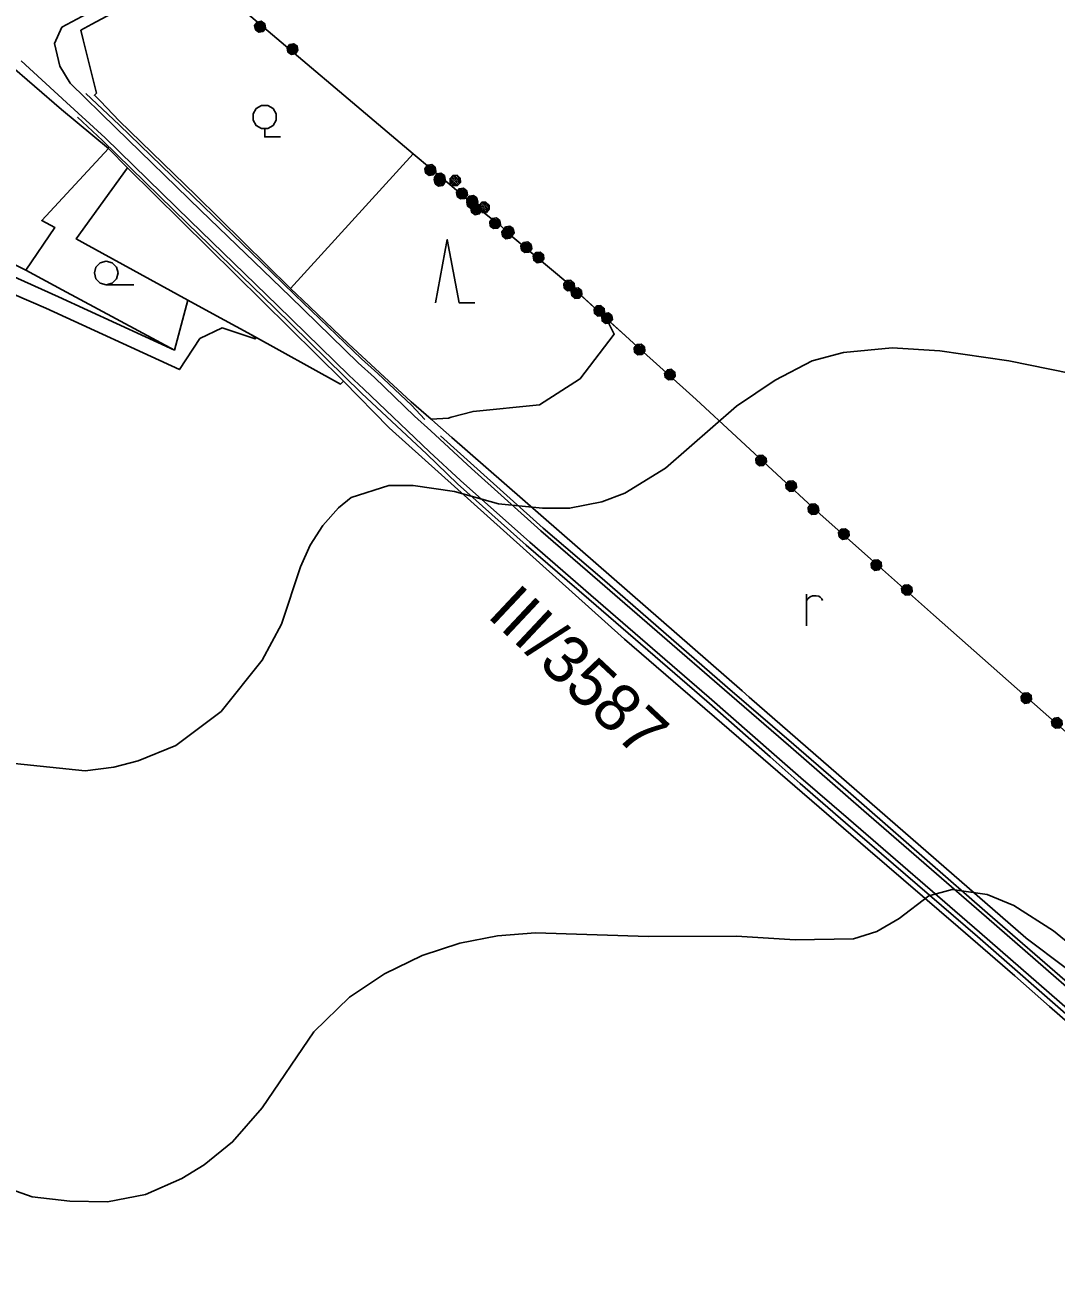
# Model space of a CAD drawing. Extents: x -645676 to -642474, y -1077513 to -1072613.
# Drawn here: x -643348.1 to -643021.2, y -1073485.7 to -1073092.2 of the extents above; entities that cross this region are included whole.
import ezdxf

# ---------------------------------------------------------------- set-up
doc = ezdxf.new("R2010")
doc.units = 0
for name, color, linetype in [('KULTURY_STAV', 7, 'Continuous'), ('KULTURY_ZNACKY', 7, 'Continuous'), ('Obvod_KP_', 7, 'Continuous'), ('OBVOD_PU', 7, 'Continuous'), ('P__kop___st_vaj_c_', 7, 'Continuous'), ('Popis_silnice_II__a_III__t__dy', 7, 'Continuous'), ('Silnice_II__t__dy_a_III__t__dy', 7, 'Continuous'), ('SPRAV_HR_STAV', 7, 'Continuous'), ('VRSTEVNICE', 7, 'Continuous')]:
    doc.layers.add(name, color=color, linetype=linetype)

# ---------------------------------------------------------------- blocks, each defined once
blk = doc.blocks.new('3$0400')
blk.add_lwpolyline([(0, 0), (-0.38, 0.1), (-0.65, 0.38), (-0.75, 0.75), (-0.65, 1.12), (-0.38, 1.4), (0, 1.5), (0.38, 1.4), (0.65, 1.12), (0.75, 0.75), (0.65, 0.38), (0.38, 0.1), (0, 0), (1.75, 0)])
blk = doc.blocks.new('3$0800')
blk.add_lwpolyline([(-0.75, 0), (0, 4), (0.75, 0), (1.75, 0)])
blk = doc.blocks.new('3$0500')
blk.add_lwpolyline([(0, 0.53), (-0.19, 0.53), (-0.53, 0.72), (-0.72, 1.06), (-0.72, 1.45), (-0.53, 1.79), (-0.19, 1.98), (0.2, 1.98), (0.54, 1.79), (0.73, 1.45), (0.73, 1.06), (0.54, 0.72), (0.2, 0.53), (0.01, 0.53), (0.01, 0), (1.01, 0)])
blk = doc.blocks.new('$479')
for points in [[(0, 0), (0, 1.27), (0, 2)], [(0, 1.6), (0.1, 1.73), (0.23, 1.84), (0.37, 1.89), (0.6, 1.9), (0.77, 1.87), (0.87, 1.8), (0.96, 1.7), (1, 1.6)]]:
    blk.add_lwpolyline(points)
blk = doc.blocks.new('2$0620')
for points in [[(-1.07, 0.32), (-0.88, 0.13), (-0.88, -0.14), (-1.07, -0.33), (-1.34, -0.33), (-1.53, -0.14), (-1.53, 0.13), (-1.34, 0.32), (-1.07, 0.32), (-1.08, 0.28), (-1.32, 0.28), (-1.4, 0.2), (-1, 0.2), (-0.92, 0.12), (-1.48, 0.12), (-1.48, 0.04), (-0.92, 0.04), (-0.92, -0.04), (-1.48, -0.04), (-1.48, -0.12), (-0.92, -0.12), (-1, -0.2), (-1.4, -0.2), (-1.32, -0.28), (-1.08, -0.28)], [(1.43, 0.32), (1.62, 0.13), (1.62, -0.14), (1.43, -0.33), (1.16, -0.33), (0.97, -0.14), (0.97, 0.13), (1.16, 0.32), (1.43, 0.32), (1.4, 0.28), (1.16, 0.28), (1.08, 0.2), (1.48, 0.2), (1.56, 0.12), (1, 0.12), (1, 0.04), (1.56, 0.04), (1.56, -0.04), (1, -0.04), (1, -0.12), (1.56, -0.12), (1.48, -0.2), (1.08, -0.2), (1.16, -0.28), (1.4, -0.28)]]:
    blk.add_lwpolyline(points)

msp = doc.modelspace()

# ---------------------------------------------------------------- linework, layer by layer
at = {"layer": 'KULTURY_STAV'}
for points in [[(-643296.21, -1073075.68), (-643290.86, -1073080.01), (-643287.81, -1073082.47), (-643285.35, -1073084.46), (-643283.33, -1073083.76), (-643281.92, -1073084.95), (-643224.95, -1073133.07), (-643263.86, -1073175.83), (-643261.75, -1073177.84), (-643263.86, -1073175.83), (-643293.86, -1073146.22), (-643318.19, -1073122.63), (-643324.08, -1073116.41), (-643326.04, -1073114.54), (-643325.4, -1073113.94), (-643329.62, -1073096.96), (-643330.38, -1073093.93), (-643326.83, -1073092.03), (-643317.54, -1073087.07), (-643312.22, -1073084.23), (-643296.21, -1073075.68)], [(-643326.83, -1073092.03), (-643330.38, -1073093.93), (-643329.62, -1073096.96), (-643325.4, -1073113.94), (-643326.04, -1073114.54), (-643324.08, -1073116.41), (-643318.19, -1073122.63), (-643293.86, -1073146.22), (-643263.86, -1073175.83), (-643261.75, -1073177.84), (-643260.18, -1073179.33), (-643245.44, -1073193.33), (-643225.66, -1073211.67), (-643219.31, -1073217.22), (-643218.12, -1073218.26), (-643212.7, -1073223), (-643167.1, -1073262.85), (-643120.73, -1073303.37), (-643118.51, -1073305.31), (-643118.49, -1073305.33), (-643030.79, -1073381.65), (-643030.66, -1073381.74), (-643018.34, -1073391)], [(-643353.64, -1073104.24), (-643336.43, -1073119.05), (-643321.53, -1073131.44), (-643342.76, -1073154.27), (-643338.61, -1073156.46), (-643347.83, -1073170.04), (-643361.09, -1073163.36), (-643387.69, -1073148.03), (-643398.24, -1073141.11), (-643395.1, -1073137.94), (-643387.69, -1073131.15), (-643381.32, -1073123.85), (-643380.09, -1073122.55), (-643353.64, -1073104.24)], [(-642998.75, -1073424.71), (-643023.32, -1073403.36), (-643034.23, -1073393.69), (-643052.25, -1073378.17), (-643080.91, -1073353.5), (-643157.97, -1073286.97), (-643232.56, -1073219.92), (-643247.12, -1073205.19), (-643315.57, -1073137.59), (-643321.53, -1073131.44), (-643336.43, -1073119.05), (-643353.64, -1073104.24)], [(-643321.53, -1073131.44), (-643315.57, -1073137.59), (-643331.82, -1073160.06), (-643328.97, -1073161.67), (-643296.42, -1073179.5), (-643300.68, -1073195.31), (-643336.26, -1073176.27), (-643347.83, -1073170.04), (-643338.61, -1073156.46), (-643342.76, -1073154.27), (-643321.53, -1073131.44)], [(-643224.95, -1073133.07), (-643213.42, -1073142.81), (-643210.36, -1073145.39), (-643200.78, -1073153.18), (-643197.26, -1073155.82), (-643194.66, -1073158.46), (-643180.49, -1073170.32), (-643176.63, -1073173.56), (-643163.66, -1073185.4), (-643161.27, -1073190.23), (-643172.2, -1073204.57), (-643172.22, -1073204.59), (-643184.91, -1073212.67), (-643206, -1073214.78), (-643212.98, -1073216.56), (-643213.8, -1073216.91), (-643219.31, -1073217.22), (-643225.66, -1073211.67), (-643245.44, -1073193.33), (-643260.18, -1073179.33), (-643261.75, -1073177.84), (-643263.86, -1073175.83), (-643224.95, -1073133.07)], [(-643376.35, -1073167.01), (-643341.42, -1073182.01), (-643299.07, -1073201.52), (-643292.57, -1073191.65), (-643285.58, -1073188.29), (-643275.03, -1073191.76), (-643274.84, -1073191.47), (-643276.29, -1073190.5), (-643289.7, -1073183.18), (-643296.42, -1073179.5), (-643328.97, -1073161.67), (-643331.82, -1073160.06), (-643315.57, -1073137.59)], [(-643315.57, -1073137.59), (-643247.12, -1073205.19), (-643232.56, -1073219.92), (-643157.97, -1073286.97), (-643080.91, -1073353.5), (-643052.25, -1073378.17), (-643034.23, -1073393.69), (-643023.32, -1073403.36), (-642998.75, -1073424.71), (-642972.5, -1073447.63), (-642919.91, -1073493.56)], [(-643405.6, -1073150.8), (-643361.09, -1073163.36), (-643347.83, -1073170.04), (-643336.26, -1073176.27), (-643300.68, -1073195.31), (-643337.38, -1073178.47), (-643371.97, -1073162.86), (-643405.6, -1073150.8)], [(-643371.97, -1073162.86), (-643337.38, -1073178.47), (-643300.68, -1073195.31), (-643296.42, -1073179.5), (-643289.7, -1073183.18), (-643276.29, -1073190.5), (-643274.84, -1073191.47), (-643275.03, -1073191.76), (-643285.58, -1073188.29), (-643292.57, -1073191.65), (-643299.07, -1073201.52), (-643341.42, -1073182.01), (-643376.35, -1073167.01)], [(-643018.34, -1073391), (-643030.66, -1073381.74), (-643030.79, -1073381.65), (-643118.49, -1073305.33), (-643118.51, -1073305.31), (-643120.73, -1073303.37), (-643167.1, -1073262.85), (-643212.7, -1073223), (-643218.12, -1073218.26), (-643219.31, -1073217.22), (-643213.8, -1073216.91), (-643212.98, -1073216.56), (-643206, -1073214.78), (-643184.91, -1073212.67), (-643172.22, -1073204.59), (-643172.2, -1073204.57), (-643161.27, -1073190.23), (-643163.66, -1073185.4)], [(-643163.66, -1073185.4), (-643157.69, -1073190.84), (-643155.17, -1073193.1), (-643135.23, -1073210.97), (-643096.95, -1073246.45), (-643080.03, -1073261.47), (-643060.08, -1073279.19), (-643012.51, -1073321.33)]]:
    msp.add_lwpolyline(points, dxfattribs=at)
at = {"layer": 'Obvod_KP_'}
msp.add_lwpolyline([(-643336.43, -1073119.05), (-643353.64, -1073104.24), (-643380.09, -1073122.55), (-643381.32, -1073123.85), (-643387.69, -1073131.15), (-643395.1, -1073137.94), (-643398.24, -1073141.11), (-643405.6, -1073150.8), (-643371.97, -1073162.86), (-643337.38, -1073178.47), (-643300.68, -1073195.31), (-643296.42, -1073179.5), (-643289.7, -1073183.18), (-643276.29, -1073190.5), (-643248, -1073206.11), (-643247.12, -1073205.19), (-643315.57, -1073137.59), (-643321.53, -1073131.44)], close=True, dxfattribs=at)
at = {"layer": 'OBVOD_PU'}
for points in [[(-643281.92, -1073084.95), (-643224.95, -1073133.07), (-643213.42, -1073142.81), (-643210.36, -1073145.39), (-643200.78, -1073153.18), (-643197.26, -1073155.82), (-643194.66, -1073158.46), (-643180.49, -1073170.32), (-643176.63, -1073173.56), (-643157.69, -1073190.84), (-643155.17, -1073193.1), (-643135.23, -1073210.97), (-643096.95, -1073246.45), (-643080.03, -1073261.47), (-643060.08, -1073279.19), (-643012.51, -1073321.33)], [(-643353.64, -1073104.24), (-643336.43, -1073119.05), (-643321.53, -1073131.44), (-643315.57, -1073137.59), (-643247.12, -1073205.19), (-643248, -1073206.11), (-643276.29, -1073190.5), (-643289.7, -1073183.18), (-643296.42, -1073179.5), (-643300.68, -1073195.31), (-643337.38, -1073178.47), (-643371.97, -1073162.86), (-643405.6, -1073150.8), (-643398.24, -1073141.11), (-643395.1, -1073137.94), (-643387.69, -1073131.15), (-643381.32, -1073123.85), (-643380.09, -1073122.55), (-643353.64, -1073104.24)]]:
    msp.add_lwpolyline(points, dxfattribs=at)
at = {"layer": 'P__kop___st_vaj_c_'}
for points in [[(-643328.75, -1073114.01), (-643318.18, -1073123.92), (-643291.41, -1073149.8), (-643269.85, -1073170.66), (-643262.49, -1073177.78), (-643241.36, -1073198.1), (-643236.24, -1073202.79), (-643225.57, -1073212.83), (-643221.34, -1073217.33)], [(-643331.41, -1073121.45), (-643323.49, -1073128.9), (-643296.51, -1073155.2), (-643268.97, -1073181.96), (-643241.39, -1073208.99), (-643220.67, -1073228.31), (-643210.9, -1073237.67), (-643189.19, -1073257.19), (-643169.29, -1073274.24), (-643131.93, -1073306.64), (-643111.84, -1073324.28), (-643102.27, -1073332.71), (-643087.95, -1073345.16), (-643046.13, -1073381.17), (-643014.71, -1073408.64), (-643009.2, -1073413.44), (-642996.3, -1073424.52), (-642946.02, -1073468.22), (-642920.53, -1073490.33)], [(-643216.32, -1073222.53), (-643205.74, -1073231.98), (-643183.79, -1073251.73), (-643165.04, -1073267.7), (-643125.36, -1073302.25), (-643104.34, -1073320.29), (-643087.13, -1073335.25), (-643081.2, -1073340.43), (-643042.91, -1073373.74), (-642990.74, -1073418.98)]]:
    msp.add_lwpolyline(points, dxfattribs=at)
at = {"layer": 'Silnice_II__t__dy_a_III__t__dy'}
for p, q in [((-643336.33, -1073092.94), (-643326.89, -1073087.95)), ((-643336.33, -1073092.94), (-643338.67, -1073098.17)), ((-643338.67, -1073098.17), (-643337.04, -1073105.34)), ((-643334.85, -1073116.83), (-643349.21, -1073103.67)), ((-643337.04, -1073105.34), (-643333.69, -1073110.73)), ((-643333.69, -1073110.73), (-643319.22, -1073124.93)), ((-643322.62, -1073128.09), (-643334.85, -1073116.83)), ((-643319.22, -1073124.93), (-643292.29, -1073151.1)), ((-643295.65, -1073154.33), (-643322.62, -1073128.09)), ((-643292.29, -1073151.1), (-643264, -1073178.33)), ((-643268.03, -1073181.2), (-643295.65, -1073154.33)), ((-643264, -1073178.33), (-643242.39, -1073199.38)), ((-643245.4, -1073203.29), (-643268.03, -1073181.2)), ((-643242.39, -1073199.38), (-643237.29, -1073204.04)), ((-643240.68, -1073207.72), (-643245.4, -1073203.29)), ((-643237.29, -1073204.04), (-643224.56, -1073216.23)), ((-643219.78, -1073227.6), (-643240.68, -1073207.72)), ((-643224.56, -1073216.23), (-643219.4, -1073220.88)), ((-643219.4, -1073220.88), (-643206.54, -1073232.88)), ((-643219.78, -1073227.6), (-643210.01, -1073236.65)), ((-643206.54, -1073232.88), (-643184.49, -1073252.61)), ((-643210.01, -1073236.65), (-643188.04, -1073256.2)), ((-643184.49, -1073252.61), (-643165.85, -1073268.8)), ((-643168.62, -1073273.01), (-643188.04, -1073256.2)), ((-643165.85, -1073268.8), (-643126.3, -1073302.98)), ((-643131.12, -1073305.41), (-643168.62, -1073273.01)), ((-643110.51, -1073323.52), (-643131.12, -1073305.41)), ((-643126.3, -1073302.98), (-643105.22, -1073321.21)), ((-643105.22, -1073321.21), (-643087.96, -1073336.25)), ((-643102.13, -1073330.9), (-643110.51, -1073323.52)), ((-643087.03, -1073343.87), (-643102.13, -1073330.9)), ((-643087.96, -1073336.25), (-643082.14, -1073341.39)), ((-643045.47, -1073379.86), (-643087.03, -1073343.87)), ((-643082.14, -1073341.39), (-643043.21, -1073375.08)), ((-643043.21, -1073375.08), (-642991.51, -1073420.14)), ((-643013.58, -1073407.57), (-643045.47, -1073379.86))]:
    msp.add_line(p, q, dxfattribs=at)
at = {"layer": 'SPRAV_HR_STAV'}
for p, q in [((-643281.92, -1073084.95), (-643224.95, -1073133.07)), ((-643224.95, -1073133.07), (-643213.42, -1073142.81)), ((-643213.42, -1073142.81), (-643210.36, -1073145.39)), ((-643200.78, -1073153.18), (-643210.36, -1073145.39)), ((-643197.26, -1073155.82), (-643200.78, -1073153.18)), ((-643194.66, -1073158.46), (-643197.26, -1073155.82)), ((-643180.49, -1073170.32), (-643194.66, -1073158.46)), ((-643176.63, -1073173.56), (-643180.49, -1073170.32)), ((-643157.69, -1073190.84), (-643176.63, -1073173.56)), ((-643155.17, -1073193.1), (-643157.69, -1073190.84)), ((-643135.23, -1073210.97), (-643155.17, -1073193.1)), ((-643096.95, -1073246.45), (-643135.23, -1073210.97)), ((-643080.03, -1073261.47), (-643096.95, -1073246.45)), ((-643060.08, -1073279.19), (-643080.03, -1073261.47)), ((-643012.51, -1073321.33), (-643060.08, -1073279.19))]:
    msp.add_line(p, q, dxfattribs=at)
at = {"layer": 'VRSTEVNICE'}
for points in [[(-643351.32, -1073326.35), (-643328.96, -1073328.63), (-643319.85, -1073327.49), (-643312.16, -1073325.5), (-643300.19, -1073320.66), (-643285.81, -1073309.83), (-643272.85, -1073293.6), (-643266.72, -1073282.2), (-643260.74, -1073263.97), (-643257.61, -1073257.14), (-643253.62, -1073250.87), (-643248.64, -1073245.32), (-643244.65, -1073242.04), (-643232.68, -1073238.2), (-643224.99, -1073238.2), (-643211.89, -1073240.19), (-643197.93, -1073244.03), (-643183.98, -1073245.46), (-643175.43, -1073245.46), (-643165.18, -1073243.46), (-643157.91, -1073240.62), (-643144.95, -1073232.78), (-643122.45, -1073213.13), (-643110.2, -1073204.87), (-643098.52, -1073198.74), (-643088.55, -1073196.04), (-643073.17, -1073194.61), (-643058.08, -1073195.61), (-643036.14, -1073198.74), (-643010.22, -1073204.01)], [(-643014.49, -1073385.49), (-643022.04, -1073379.36), (-643034.58, -1073371.39), (-643042.98, -1073367.83), (-643054.09, -1073366.26), (-643061.49, -1073368.25), (-643070.89, -1073375.52), (-643078.01, -1073379.65), (-643085.42, -1073381.93), (-643103.94, -1073382.21), (-643122.45, -1073381.07), (-643150.36, -1073381.21), (-643186.25, -1073380.07), (-643198.22, -1073380.93), (-643210.18, -1073383.35), (-643222.15, -1073387.2), (-643234.11, -1073393.03), (-643245.22, -1073400.44), (-643256.47, -1073411.41), (-643272.85, -1073435.48), (-643282.25, -1073446.3), (-643291.22, -1073453.56), (-643298.34, -1073457.84), (-643309.88, -1073462.96), (-643321.84, -1073465.24), (-643333.8, -1073465.1), (-643345.77, -1073463.68), (-643361.72, -1073458.12)]]:
    msp.add_lwpolyline(points, dxfattribs=at)

# ---------------------------------------------------------------- block references
at = {"layer": 'KULTURY_ZNACKY', "xscale": 5, "yscale": 5}
for name, p in [('3$0500', (-643272.09, -1073127.74)), ('3$0800', (-643214.2, -1073180.3)), ('3$0400', (-643322.31, -1073174.63)), ('$479', (-643100.27, -1073282.68))]:
    msp.add_blockref(name, p, dxfattribs=at)
at = {"layer": 'SPRAV_HR_STAV'}
for p, xscale, yscale, rotation in [((-643268.55, -1073096.24), 5, 5, -34.60448), ((-643214.36, -1073142.14), 5, 5, 143.34251799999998), ((-643211.26, -1073145.32), 4.999999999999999, 4.999999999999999, 145.628189), ((-643211.58, -1073144.36), 5, 5, -34.607788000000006), ((-643206.94, -1073145.99), 5.000000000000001, 5, 136.911197), ((-643200.04, -1073154.09), 5, 5, -34.552803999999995), ((-643193.91, -1073159.09), 5, 5, 142.516068), ((-643190.03, -1073162.31), 5, 5, 142.43392599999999), ((-643170.62, -1073179.05), 5, 5, 140.026084), ((-643168.2, -1073181.42), 5, 5, 140.523967), ((-643148.26, -1073199.29), 4.999999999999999, 5, 140.544551), ((-643109.78, -1073234.55), 5, 4.999999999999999, 139.568091), ((-643093.12, -1073249.85), 5, 4.999999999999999, 140.81992799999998), ((-643073.16, -1073267.57), 5, 4.999999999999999, 140.80318), ((-643025.61, -1073309.73), 5, 4.999999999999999, 140.880443)]:
    msp.add_blockref('2$0620', p, dxfattribs=dict(at, xscale=xscale, yscale=yscale, rotation=rotation))

# ---------------------------------------------------------------- texts
at = {"layer": 'Popis_silnice_II__a_III__t__dy'}
msp.add_text('III/3587', height=15, rotation=316.799, dxfattribs=at).set_placement((-643201.94, -1073279.66))

doc.saveas('drawing.dxf')
